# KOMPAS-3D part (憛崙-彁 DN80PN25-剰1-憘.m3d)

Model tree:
1. Объединить компоненты:1  (labels: СЕНС-ПР DN80PN25-ДП1)
2. Эскиз:1
3. Операция выдавливания:1
     Расстояние 1 = 14
4. Фаска:1
     Угол = 45; Длина 1 = 2; Длина 2 = 2

Referenced files in D:\Савин\!СЕНСОР\3D для заказчика\!Новый перечень\СЕНС-ПР\3. СЕНС-ПР-ДП\DN80\: СЕНС-ПР DN80PN25-ДП1.a3d
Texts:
  СЕНС-ПР DN80PN25-ДП1-СВ
  ООО НПП Сенсор
  СЕНС-ПР DN80PN25-ДП1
